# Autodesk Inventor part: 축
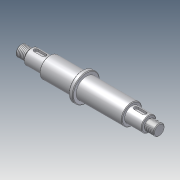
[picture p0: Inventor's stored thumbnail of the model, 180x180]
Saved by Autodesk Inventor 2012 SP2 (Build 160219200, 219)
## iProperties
Company: 한국ATC센터
Created: 2015-02
Part Number: 축
Document SubType Name: Modeling
Designer: KYOUNG IL JANG
Density: 1 g/cm^3
Material: 기본값
Author: KYOUNG IL JANG
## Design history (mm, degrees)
sketch "스케치1"
  geometry: L1 (0, 0)-(203, 0); L2 (203, 0)-(203, 8); L3 (203, 8)-(189.5, 8); L4 (189.5, 8)-(189.5, 7); L5 (189.5, 7)-(188, 7); L6 (188, 7)-(188, 11); L7 (188, 11)-(163, 11); L8 (163, 11)-(163, 15); L9 (163, 15)-(96, 15); L10 (96, 15)-(96, 20); L11 (96, 20)-(90, 20); L12 (90, 20)-(90, 15); L13 (90, 15)-(42, 15); L14 (42, 15)-(42, 11); L15 (42, 11)-(15, 11); L16 (15, 11)-(15, 7); L17 (15, 7)-(13.5, 7); L18 (0, 8)-(0, 0); L19 (0, 8)-(13.5, 8); L20 (13.5, 8)-(13.5, 7)
  constraints: 40 end point, 16 parallel, 3 perpendicular, 1 collinear, 1 horizontal
  dimensions: "d0" = 16 diameter of L3 L1; "d1" = 14 diameter of L5 L1; "d2" = 22 diameter of L7 L1; "d3" = 30 diameter of L9 L1; "d4" = 40 diameter of L11 L1; "d5" = 16 diameter of L19 L1; "d6" = 22 diameter of L15 L1; "d8" = 1.5 distance of L16.end L17.end; "d9" = 15 distance between parallel lines of L16 L18; "d10" = 27 distance between parallel lines of L14 L16; "d11" = 48 distance between parallel lines of L12 L14; "d15" = 203 distance of L1.start L1.end; "d16" = 1.5 distance of L4.end L5.end; "d17" = 14 diameter of L17 L1; "d36" = 15 distance between parallel lines of L6 L2; "d37" = 25 distance between parallel lines of L6 L8; "d38" = 6 distance between parallel lines of L10 L12
revolve "회전1" sketch "스케치1" stored, may be unused: angle "d18" = 90 deg
feature "스레드1" dims "d19" = 10, "d20" = 0
feature "스레드2" dims "d21" = 10, "d22" = 0
chamfer "모따기1" distance "d23" = 1; stored, may be unused: second distance "d24" = 2, angle "d25" = 45 deg
node "작업 평면1"
sketch "스케치2"
  geometry: L1 (-6.5, 3)-(5.5, 3); L2 (5.5, -3)-(-6.5, -3); L3 (-13.5, -10)-(-13.5, 10) reference; L4 (140.5, 3)-(152.5, 3); L5 (152.5, -3)-(140.5, -3); L6 (159.5, 10)-(159.5, -10) reference; A1 r 3 centre (5.5, 0) between (5.5, -3) and (5.5, 3); A2 r 3 centre (-6.5, 0) between (-6.5, 3) and (-6.5, -3); A3 r 3 centre (152.5, 0) between (152.5, -3) and (152.5, 3); A4 r 3 centre (140.5, 0) between (140.5, 3) and (140.5, -3); 1 further point
  constraints: 8 end point, 8 point on circle, 8 tangent, 4 centre point, 2 horizontal, 2 horizontal alignment, 2 parallel
  dimensions: "d26" = 6 distance between parallel lines of L2 L1; "d27" = 18 dimension on A1 A2; "d28" = 4 distance edge to line of A2 L3; "d29" = 6 distance between parallel lines of L5 L4; "d30" = 18 dimension on A3 A4; "d31" = 4 distance edge to line of A3 L6
extrude "돌출1" cut sketch "스케치2" distance "d32" = 3.5; taper "d33" = 0 deg
node "솔리드1"
